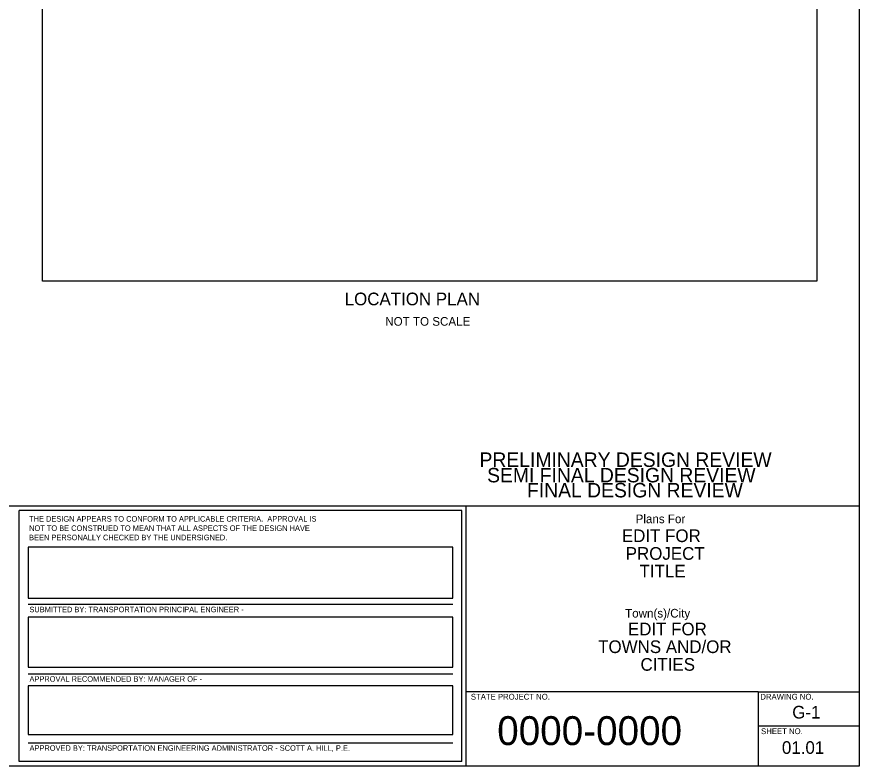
# Model space of a CAD drawing. Extents: x 0 to 2603, y -226 to 830.
# Drawn here: x 803.8 to 1270, y 0 to 415 of the extents above; entities that cross this region are included whole.
import ezdxf

# ---------------------------------------------------------------- set-up
doc = ezdxf.new("R2010")
doc.units = 0
for name, color, linetype in [('CT_Bdr_Txt_Titleblock', 7, 'Continuous'), ('CT_Border_Perimeter_Shape', 7, 'Continuous'), ('CT_DigSig_Field1', 7, 'Continuous'), ('CT_Note_Final_Design_Review', 7, 'Continuous'), ('CT_Note_Preliminary_Design_Review', 7, 'Continuous'), ('CT_Note_Semi_Final_Design_Review', 7, 'Continuous'), ('CT_TSH_Annotation _Location_Plan', 7, 'Continuous'), ('CT_TSH_Annotation_Edit', 7, 'Continuous'), ('CT_TSH_Annotation_Locked', 7, 'Continuous'), ('CT_TSH_Annotation_Written_Signatures', 7, 'Continuous'), ('CT_TSH_Line_Work_Approval_Block', 7, 'Continuous'), ('CT_TSH_Line_Work_Major', 7, 'Continuous'), ('CT_TSH_Line_Work_Minor', 7, 'Continuous'), ('CT_TSH_Map_Location_Plan_Border', 7, 'Continuous')]:
    doc.layers.add(name, color=color, linetype=linetype)

msp = doc.modelspace()

# ---------------------------------------------------------------- linework, layer by layer
at = {"layer": 'CT_Border_Perimeter_Shape'}
msp.add_lwpolyline([(0, 830), (1270, 830), (1270, 0), (0, 0)], close=True, dxfattribs=at)
at = {"layer": 'CT_DigSig_Field1'}
for points in [[(810.02, 93.06), (1045.01, 93.06), (1045.01, 121.2), (810.02, 121.2)], [(810.02, 54.76), (1045.01, 54.76), (1045.01, 82.58), (810.02, 82.58)], [(810.02, 17.51), (1045.01, 17.51), (1045.01, 44.4), (810.02, 44.4)]]:
    msp.add_lwpolyline(points, close=True, dxfattribs=at)
at = {"layer": 'CT_TSH_Annotation_Written_Signatures'}
for p, q in [((810.02, 89.74), (1045.01, 89.74)), ((810.02, 51.13), (1045.01, 51.13)), ((810.02, 12.94), (1045.01, 12.94))]:
    msp.add_line(p, q, dxfattribs=at)
at = {"layer": 'CT_TSH_Line_Work_Approval_Block'}
for p, q in [((1050.01, 141.6), (805.02, 141.6)), ((805.02, 2.5), (805.02, 141.6)), ((1050.01, 2.5), (1050.01, 141.6)), ((1050.01, 2.5), (805.02, 2.5))]:
    msp.add_line(p, q, dxfattribs=at)
at = {"layer": 'CT_TSH_Line_Work_Major'}
for p, q in [((246.75, 144.1), (1270, 144.1)), ((1052.52, 0), (1052.52, 144.1))]:
    msp.add_line(p, q, dxfattribs=at)
at = {"layer": 'CT_TSH_Line_Work_Minor'}
for p, q in [((1214.02, 41.25), (1052.52, 41.25)), ((1214.02, 41.25), (1270, 41.25)), ((1214.02, 41.25), (1214.02, 0)), ((1214.02, 22.26), (1270, 22.26))]:
    msp.add_line(p, q, dxfattribs=at)
at = {"layer": 'CT_TSH_Map_Location_Plan_Border'}
msp.add_lwpolyline([(818.03, 693.64), (1246.64, 693.64), (1246.64, 268.56), (818.03, 268.56)], close=True, dxfattribs=at)

# ---------------------------------------------------------------- texts
at = {"layer": 'CT_Bdr_Txt_Titleblock'}
for s, p in [('G-1', (1232.97, 26.39)), ('01.01', (1227.25, 6.81))]:
    msp.add_text(s, height=7, dxfattribs=at).set_placement(p)
at = {"layer": 'CT_Note_Final_Design_Review'}
msp.add_text('FINAL DESIGN REVIEW', height=8, dxfattribs=at).set_placement((1086.15, 148.85))
at = {"layer": 'CT_Note_Preliminary_Design_Review'}
msp.add_text('PRELIMINARY DESIGN REVIEW', height=8, rotation=360, dxfattribs=at).set_placement((1059.85, 165.74))
at = {"layer": 'CT_Note_Semi_Final_Design_Review'}
msp.add_text('SEMI FINAL DESIGN REVIEW', height=8, dxfattribs=at).set_placement((1064.08, 157.18))
at = {"layer": 'CT_TSH_Annotation _Location_Plan'}
for s, height, p in [('LOCATION PLAN', 7, (985.23, 255.26)), ('NOT TO SCALE', 4.8, (1007.69, 243.92))]:
    msp.add_text(s, height=height, rotation=360, dxfattribs=at).set_placement(p)
at = {"layer": 'CT_TSH_Annotation_Edit'}
for s, height, p in [('EDIT FOR', 7, (1138.66, 124.11)), ('PROJECT', 7, (1140.8, 114.31)), ('TITLE', 7, (1148.43, 104.51)), ('Town(s)/City', 4.8, (1140.45, 82.3)), ('EDIT FOR ', 7, (1142.01, 72.45)), ('TOWNS AND/OR ', 7, (1125.54, 62.65)), ('CITIES', 7, (1148.96, 52.85)), ('0000-0000', 16, (1069.66, 11.67))]:
    msp.add_text(s, height=height, dxfattribs=at).set_placement(p)
at = {"layer": 'CT_TSH_Annotation_Locked'}
for s, height, p in [('Plans For', 4.8, (1146.28, 134.56)), ('DRAWING NO.', 3.2, (1215.3, 36.85)), ('SHEET NO.', 3.2, (1215.72, 17.75))]:
    msp.add_text(s, height=height, dxfattribs=at).set_placement(p)
msp.add_text('STATE PROJECT NO.', height=3.2, rotation=360, dxfattribs=at).set_placement((1055.07, 36.85))
at = {"layer": 'CT_TSH_Annotation_Written_Signatures'}
for s, p in [('SUBMITTED BY: TRANSPORTATION PRINCIPAL ENGINEER -', (810.72, 85.24)), ('APPROVAL RECOMMENDED BY: MANAGER OF - ', (810.76, 46.75)), ('APPROVED BY: TRANSPORTATION ENGINEERING ADMINISTRATOR - SCOTT A. HILL, P.E.', (810.8, 8.5))]:
    msp.add_text(s, height=3.0756, dxfattribs=at).set_placement(p)
at = {"layer": 'CT_TSH_Line_Work_Approval_Block'}
for s, p in [('THE DESIGN APPEARS TO CONFORM TO APPLICABLE CRITERIA.  APPROVAL IS', (810.55, 135.42)), ('NOT TO BE CONSTRUED TO MEAN THAT ALL ASPECTS OF THE DESIGN HAVE ', (810.55, 130.27)), ('BEEN PERSONALLY CHECKED BY THE UNDERSIGNED.', (810.55, 125.12))]:
    msp.add_text(s, height=3.0756, dxfattribs=at).set_placement(p)

doc.saveas('drawing.dxf')
